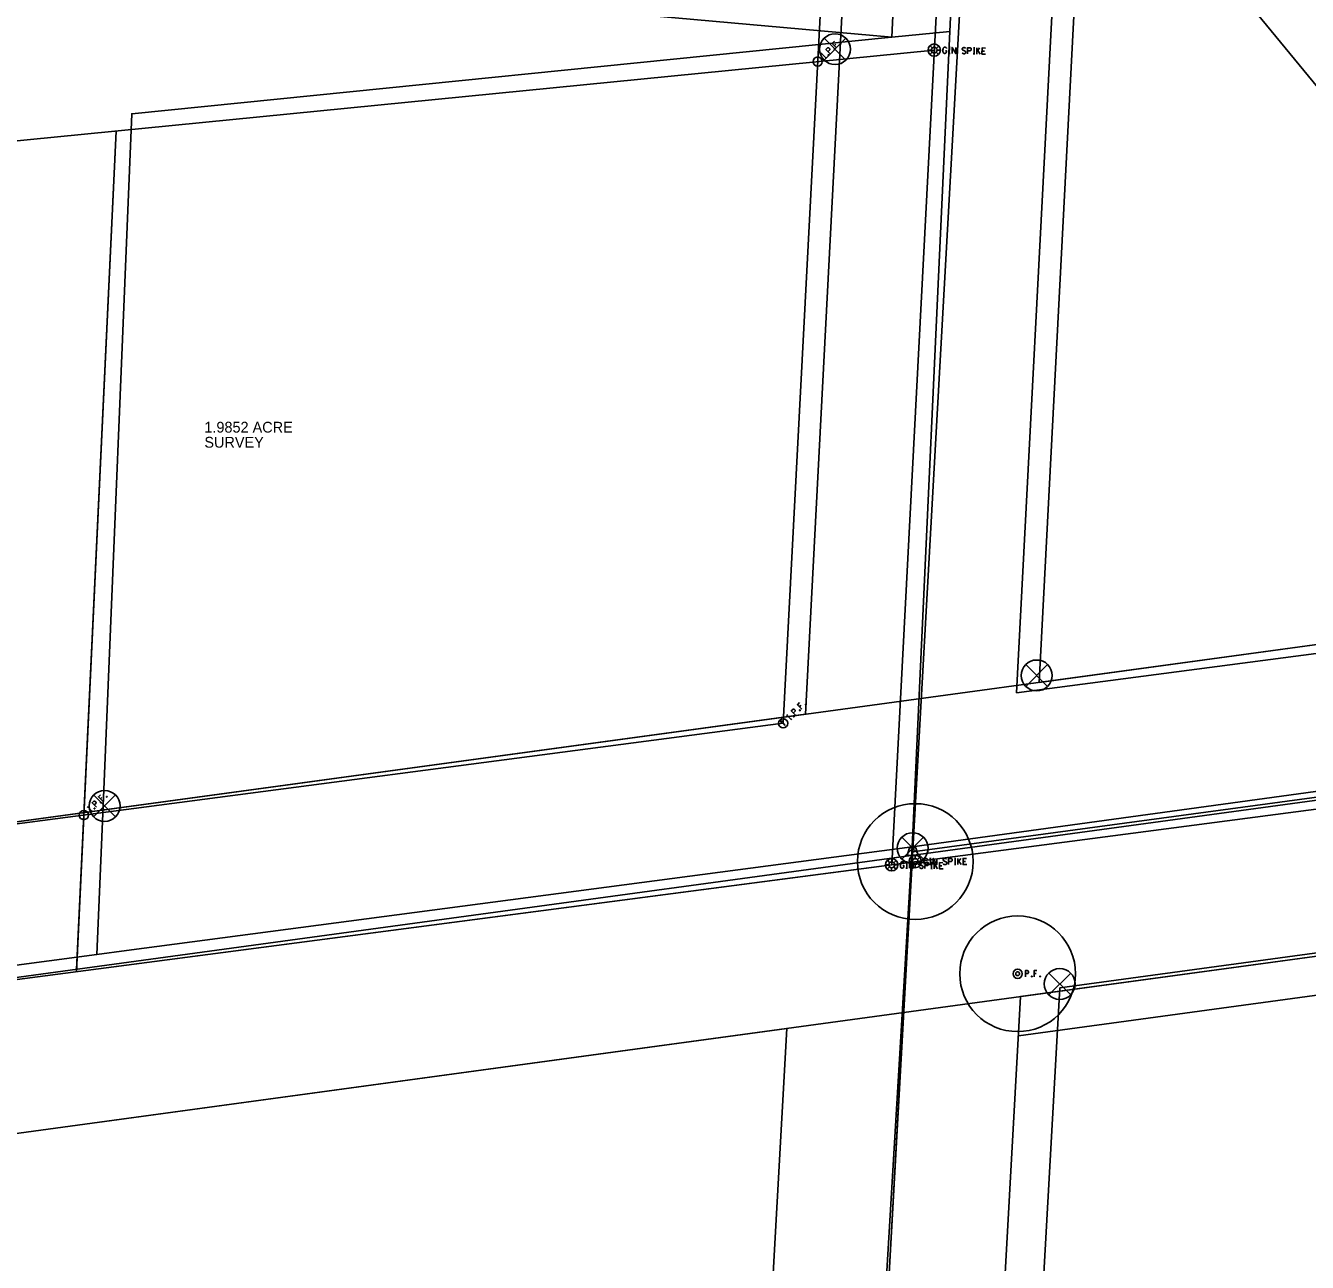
# Model space of a CAD drawing. Extents: x 1532954 to 1577849, y 698998 to 706606.
# Drawn here: x 1571701.2 to 1572033.3, y 702780.4 to 703100.9 of the extents above; entities that cross this region are included whole.
import ezdxf

# ---------------------------------------------------------------- set-up
doc = ezdxf.new("R2010")
doc.units = 0
for name, color, linetype in [('Default', 7, 'Continuous'), ('DV_X_Lot_Line', 7, 'Continuous'), ('GM_X_Major_Lake_Text', 7, 'Continuous'), ('RW_X_Esmt_SH', 7, 'Continuous'), ('RW_X_Esmt_U', 7, 'Continuous'), ('SC_Scratch1', 7, 'Continuous'), ('SC_Scratch10', 7, 'Continuous'), ('SC_Scratch2', 7, 'Continuous'), ('SC_Scratch3', 7, 'Continuous'), ('SC_Scratch9', 7, 'Continuous'), ('SV_X_Control_Cells_Found', 7, 'Continuous'), ('SV_X_Mon_Cells_Found', 7, 'Continuous')]:
    doc.layers.add(name, color=color, linetype=linetype)

msp = doc.modelspace()

# ---------------------------------------------------------------- linework, layer by layer
at = {"layer": 'Default'}
for p, q in [((1571908.1, 703097.6), (1571913.76, 703091.94)), ((1571908.1, 703091.94), (1571913.76, 703097.6)), ((1571910.93, 703094.77), (1571910.93, 703094.77)), ((1571960.35, 702935.33), (1571966.01, 702929.67)), ((1571960.35, 702929.67), (1571966.01, 702935.33)), ((1571963.18, 702932.5), (1571963.18, 702932.5)), ((1571718.87, 702901.53), (1571724.53, 702895.87)), ((1571718.87, 702895.87), (1571724.53, 702901.53)), ((1571721.7, 702898.7), (1571721.7, 702898.7)), ((1571928.21, 702890.57), (1571933.87, 702884.92)), ((1571928.21, 702884.92), (1571933.87, 702890.57)), ((1571931.04, 702887.75), (1571931.04, 702887.75)), ((1571966.32, 702855.4), (1571971.98, 702849.75)), ((1571966.32, 702849.75), (1571971.98, 702855.4)), ((1571969.15, 702852.58), (1571969.15, 702852.58))]:
    msp.add_line(p, q, dxfattribs=at)
for centre in [(1571910.93, 703094.77), (1571963.18, 702932.5), (1571721.7, 702898.7), (1571931.04, 702887.75), (1571969.15, 702852.58)]:
    msp.add_circle(centre, 4, dxfattribs=at)
at = {"layer": 'DV_X_Lot_Line'}
for p, q in [((1571623.65, 703063.55), (1571936.64, 703094.53)), ((1571714.44, 702856.35), (1571724.66, 703073.55))]:
    msp.add_line(p, q, dxfattribs=at)
at = {"layer": 'GM_X_Major_Lake_Text'}
msp.add_line((1571772.95, 700058.9), (1572138.98, 706606.16), dxfattribs=at)
at = {"layer": 'RW_X_Esmt_SH'}
for p, q in [((1571903.27, 702922.46), (1571924.71, 703332.97)), ((1571963.78, 702930.71), (1571984.64, 703330.02)), ((1571959, 702849.32), (1574870.56, 703246.15)), ((1571963.78, 702930.71), (1573359.47, 703120.93)), ((1571490.9, 702866.26), (1571903.27, 702922.46)), ((1571501.71, 702786.99), (1571898.44, 702841.06))]:
    msp.add_line(p, q, dxfattribs=at)
at = {"layer": 'RW_X_Esmt_U'}
for p, q in [((1571958.43, 702839.15), (1572381.44, 702896.8)), ((1571941.24, 702531.66), (1571959, 702849.32)), ((1571881.33, 702535.01), (1571898.44, 702841.06))]:
    msp.add_line(p, q, dxfattribs=at)
at = {"layer": 'SC_Scratch1'}
for points in [[(1571928.39, 703157.53), (1571925.61, 703097.85), (1571726.23, 703115.79), (1571727.99, 703153.75), (1571729.92, 703195.11), (1571729.92, 703195.11), (1571929.3, 703177.17), (1571929.3, 703177.17)], [(1572183.37, 702922.76), (1571930.88, 702888.14), (1571940.7, 703099.36), (1571941.66, 703120.07), (1571956.64, 703119.37), (1572131.42, 703111.24), (1572209.37, 703107.62), (1572202.78, 702965.79), (1572200.89, 702925.16)], [(1571930.88, 702888.14), (1571930.88, 702888.14), (1571727.41, 702861.2), (1571719.71, 702860.18), (1571721.39, 702900.76), (1571728.74, 703078.05), (1571925.59, 703097.85), (1571925.61, 703097.85), (1571940.7, 703099.36)], [(1572165.51, 702622.06), (1571940.9, 702635.26), (1571915.94, 702636.73), (1571918.93, 702687.02), (1571930.88, 702888.14), (1572183.37, 702922.76), (1572180.96, 702882.05)], [(1571418.8, 702820.35), (1571553.44, 702838.18), (1571596.11, 702843.82), (1571719.71, 702860.18), (1571727.41, 702861.2), (1571930.88, 702888.14), (1571930.88, 702888.14), (1571918.93, 702687.02), (1571893.69, 702683.68), (1571718.08, 702660.43), (1571714.44, 702582.22), (1571704.31, 702364.37), (1571672.96, 702360.06), (1571672.96, 702360.06), (1571530.3, 702340.45), (1571347.01, 702315.24), (1571371.42, 702773.73), (1571373.59, 702814.37)]]:
    msp.add_lwpolyline(points, close=True, dxfattribs=at)
at = {"layer": 'SC_Scratch10'}
for p, q in [((1571190.11, 702825.26), (1574958.12, 703338.82)), ((1571190.11, 702825.26), (1574958.12, 703338.82)), ((1571190.11, 702825.26), (1574958.12, 703338.82)), ((1571195.51, 702785.63), (1574963.52, 703299.19)), ((1571200.91, 702745.99), (1574968.92, 703259.55))]:
    msp.add_line(p, q, dxfattribs=at)
at = {"layer": 'SC_Scratch2'}
msp.add_line((1573640.53, 701135.41), (1571969.28, 703165.9), dxfattribs=at)
at = {"layer": 'SC_Scratch3'}
for p, q in [((1571897.48, 702920.1), (1571919.07, 703333.38)), ((1571925.61, 702883.45), (1571949.03, 703331.81)), ((1571957.98, 702928.04), (1571978.99, 703330.34)), ((1571938.76, 703135.11), (1571925.61, 702883.46)), ((1571908.52, 703131.35), (1571897.49, 702920.1)), ((1571566.93, 703057.93), (1571936.64, 703094.53)), ((1571935.89, 703094.54), (1571935.04, 703094.56)), ((1571936.09, 703094.01), (1571935.48, 703093.42)), ((1571936.12, 703095.07), (1571935.53, 703095.68)), ((1571936.62, 703093.78), (1571936.6, 703092.93)), ((1571936.65, 703095.28), (1571936.67, 703096.12)), ((1571937.16, 703093.98), (1571937.74, 703093.37)), ((1571937.18, 703095.04), (1571937.79, 703095.63)), ((1571937.39, 703094.51), (1571938.24, 703094.49)), ((1571714.41, 702855.73), (1571724.66, 703073.54)), ((1571931.04, 702886.78), (1572682.15, 702988.83)), ((1572198.25, 702959.58), (1571957.98, 702928.04)), ((1571931.04, 702886.78), (1572375.46, 702947.16)), ((1572196.13, 702918.96), (1571335.92, 702806.05)), ((1571897.48, 702920.1), (1571586.45, 702879.28)), ((1571897.49, 702920.1), (1571586.45, 702879.28)), ((1571897.4, 702920.19), (1571898.03, 702919.56)), ((1571969.14, 702851.59), (1572380.18, 702907.43)), ((1571931.05, 702887.87), (1571931.05, 702887.27)), ((1571816.39, 700835.98), (1571931.04, 702886.78)), ((1571925.09, 702883.99), (1571924.5, 702884.61)), ((1571925.63, 702884.2), (1571925.64, 702885.05)), ((1571926.15, 702883.97), (1571926.76, 702884.56)), ((1571925.61, 702883.45), (1571590.79, 702839.51)), ((1571924.86, 702883.47), (1571924.01, 702883.49)), ((1571925.07, 702882.93), (1571924.46, 702882.34)), ((1571925.6, 702882.7), (1571925.58, 702881.85)), ((1571926.13, 702882.91), (1571926.72, 702882.3)), ((1571926.36, 702883.44), (1571927.21, 702883.42)), ((1571856.33, 700833.75), (1571969.14, 702851.59))]:
    msp.add_line(p, q, dxfattribs=at)
for points in [[(1571910.76, 703096.8), (1571910.22, 703096.27), (1571911.32, 703095.12)], [(1571907.34, 703093.51), (1571907.59, 703093.75)], [(1571908.57, 703092.48), (1571907.46, 703093.63)], [(1571909.7, 703093.56), (1571908.59, 703094.71), (1571908.98, 703095.08), (1571909.02, 703095.11), (1571909.1, 703095.15), (1571909.14, 703095.15), (1571909.18, 703095.15), (1571909.25, 703095.14), (1571909.32, 703095.12), (1571909.41, 703095.06), (1571909.51, 703094.95), (1571909.54, 703094.91), (1571909.58, 703094.84), (1571909.61, 703094.74), (1571909.6, 703094.69), (1571909.59, 703094.64), (1571909.57, 703094.59), (1571909.52, 703094.52), (1571909.13, 703094.15)], [(1571910.74, 703094.85), (1571910.78, 703094.89), (1571910.82, 703094.9), (1571910.88, 703094.88), (1571910.92, 703094.84), (1571910.93, 703094.78), (1571910.93, 703094.74), (1571910.89, 703094.7), (1571910.85, 703094.69), (1571910.79, 703094.71), (1571910.74, 703094.75), (1571910.73, 703094.81), (1571910.74, 703094.85)], [(1571910.76, 703095.71), (1571911.15, 703096.08)], [(1571912.29, 703096.34), (1571912.33, 703096.38), (1571912.37, 703096.38), (1571912.43, 703096.37), (1571912.47, 703096.33), (1571912.48, 703096.27), (1571912.48, 703096.23), (1571912.44, 703096.19), (1571912.4, 703096.18), (1571912.34, 703096.2), (1571912.29, 703096.24), (1571912.28, 703096.3), (1571912.29, 703096.34)], [(1571939.83, 703094.95), (1571939.82, 703095.01), (1571939.78, 703095.07), (1571939.72, 703095.14), (1571939.64, 703095.21), (1571939.57, 703095.24), (1571939.52, 703095.25), (1571939.45, 703095.27), (1571939.3, 703095.27), (1571939.23, 703095.26), (1571939.2, 703095.25), (1571939.15, 703095.22), (1571939.04, 703095.15), (1571938.98, 703095.06), (1571938.94, 703094.96), (1571938.91, 703094.83), (1571938.88, 703094.62), (1571938.88, 703094.36), (1571938.88, 703094.15), (1571938.93, 703093.98), (1571939, 703093.83), (1571939.07, 703093.78), (1571939.14, 703093.72), (1571939.28, 703093.67), (1571939.42, 703093.67), (1571939.56, 703093.69), (1571939.61, 703093.72), (1571939.66, 703093.74), (1571939.71, 703093.79), (1571939.76, 703093.86), (1571939.81, 703093.98), (1571939.82, 703094.29), (1571939.55, 703094.3)], [(1571940.34, 703093.65), (1571940.74, 703093.64)], [(1571940.37, 703095.25), (1571940.77, 703095.24)], [(1571940.54, 703093.65), (1571940.57, 703095.25)], [(1571941.24, 703093.63), (1571941.27, 703095.23), (1571942.19, 703093.61), (1571942.22, 703095.21)], [(1571944.74, 703095.05), (1571944.71, 703095.07), (1571944.67, 703095.1), (1571944.56, 703095.14), (1571944.42, 703095.17), (1571944.32, 703095.17), (1571944.28, 703095.17), (1571944.12, 703095.14), (1571943.98, 703095.06), (1571943.89, 703094.96), (1571943.86, 703094.86), (1571943.86, 703094.79), (1571943.88, 703094.69), (1571943.98, 703094.6), (1571944.67, 703094.21), (1571944.73, 703094.15), (1571944.75, 703094.1), (1571944.78, 703094.03), (1571944.78, 703093.95), (1571944.76, 703093.88), (1571944.75, 703093.83), (1571944.72, 703093.76), (1571944.7, 703093.71), (1571944.67, 703093.68), (1571944.63, 703093.64), (1571944.59, 703093.61), (1571944.54, 703093.59), (1571944.5, 703093.58), (1571944.39, 703093.57), (1571944.21, 703093.57), (1571944.1, 703093.6), (1571943.94, 703093.69), (1571943.84, 703093.77)], [(1571945.25, 703093.55), (1571945.28, 703095.15), (1571945.88, 703095.14), (1571945.95, 703095.12), (1571946.03, 703095.1), (1571946.07, 703095.07), (1571946.11, 703095.05), (1571946.16, 703094.98), (1571946.19, 703094.92), (1571946.22, 703094.82), (1571946.21, 703094.67), (1571946.2, 703094.62), (1571946.17, 703094.54), (1571946.12, 703094.45), (1571946.07, 703094.42), (1571946.03, 703094.39), (1571945.97, 703094.37), (1571945.87, 703094.36), (1571945.26, 703094.37)], [(1571946.73, 703093.52), (1571947.14, 703093.51)], [(1571946.77, 703095.12), (1571947.17, 703095.11)], [(1571946.94, 703093.52), (1571946.97, 703095.12)], [(1571947.67, 703095.1), (1571947.64, 703093.5)], [(1571948.4, 703095.09), (1571947.65, 703094.08)], [(1571947.9, 703094.4), (1571948.5, 703093.49)], [(1571949.9, 703095.06), (1571949.03, 703095.07), (1571949, 703093.48), (1571949.93, 703093.46)], [(1571949.02, 703094.28), (1571949.63, 703094.27)], [(1571908.45, 703092.35), (1571908.7, 703092.6)], [(1571909.12, 703093.3), (1571909.16, 703093.33), (1571909.2, 703093.34), (1571909.26, 703093.32), (1571909.3, 703093.28), (1571909.31, 703093.22), (1571909.3, 703093.18), (1571909.26, 703093.14), (1571909.22, 703093.14), (1571909.16, 703093.15), (1571909.12, 703093.19), (1571909.11, 703093.25), (1571909.12, 703093.3)], [(1571901.72, 702925.46), (1571901.18, 702924.93), (1571902.31, 702923.79)], [(1571901.73, 702924.37), (1571902.11, 702924.76)], [(1571903.25, 702925.04), (1571903.29, 702925.08), (1571903.33, 702925.08), (1571903.39, 702925.07), (1571903.43, 702925.02), (1571903.45, 702924.97), (1571903.44, 702924.92), (1571903.4, 702924.89), (1571903.36, 702924.88), (1571903.3, 702924.89), (1571903.26, 702924.94), (1571903.24, 702925), (1571903.25, 702925.04)], [(1571898.36, 702922.11), (1571898.61, 702922.35)], [(1571899.61, 702921.1), (1571898.48, 702922.23)], [(1571899.49, 702920.97), (1571899.74, 702921.22)], [(1571900.72, 702922.21), (1571899.59, 702923.34), (1571899.96, 702923.71), (1571900.01, 702923.74), (1571900.08, 702923.78), (1571900.12, 702923.78), (1571900.17, 702923.79), (1571900.24, 702923.78), (1571900.31, 702923.75), (1571900.4, 702923.7), (1571900.5, 702923.59), (1571900.53, 702923.55), (1571900.57, 702923.48), (1571900.6, 702923.39), (1571900.59, 702923.33), (1571900.59, 702923.29), (1571900.57, 702923.23), (1571900.51, 702923.16), (1571900.14, 702922.78)], [(1571900.14, 702921.93), (1571900.18, 702921.97), (1571900.22, 702921.97), (1571900.28, 702921.96), (1571900.32, 702921.92), (1571900.34, 702921.86), (1571900.33, 702921.82), (1571900.29, 702921.78), (1571900.25, 702921.77), (1571900.19, 702921.78), (1571900.15, 702921.83), (1571900.13, 702921.89), (1571900.14, 702921.93)], [(1571901.73, 702923.52), (1571901.77, 702923.56), (1571901.81, 702923.56), (1571901.87, 702923.55), (1571901.91, 702923.51), (1571901.93, 702923.45), (1571901.92, 702923.41), (1571901.88, 702923.37), (1571901.84, 702923.36), (1571901.78, 702923.37), (1571901.74, 702923.42), (1571901.72, 702923.48), (1571901.73, 702923.52)], [(1571720.65, 702901.59), (1571720.1, 702901.06), (1571721.21, 702899.91)], [(1571720.64, 702900.5), (1571721.03, 702900.87)], [(1571722.17, 702901.13), (1571722.21, 702901.17), (1571722.25, 702901.17), (1571722.31, 702901.16), (1571722.35, 702901.12), (1571722.37, 702901.06), (1571722.36, 702901.02), (1571722.32, 702900.98), (1571722.28, 702900.97), (1571722.22, 702900.99), (1571722.18, 702901.03), (1571722.16, 702901.09), (1571722.17, 702901.13)], [(1571717.22, 702898.3), (1571717.47, 702898.54)], [(1571718.46, 702897.27), (1571717.35, 702898.42)], [(1571719.58, 702898.35), (1571718.48, 702899.5), (1571718.86, 702899.87), (1571718.91, 702899.9), (1571718.98, 702899.94), (1571719.02, 702899.94), (1571719.06, 702899.94), (1571719.14, 702899.93), (1571719.21, 702899.91), (1571719.29, 702899.85), (1571719.4, 702899.74), (1571719.42, 702899.7), (1571719.46, 702899.63), (1571719.49, 702899.53), (1571719.48, 702899.48), (1571719.48, 702899.43), (1571719.45, 702899.38), (1571719.4, 702899.31), (1571719.02, 702898.94)], [(1571719, 702898.09), (1571719.04, 702898.12), (1571719.08, 702898.13), (1571719.14, 702898.11), (1571719.18, 702898.07), (1571719.19, 702898.01), (1571719.19, 702897.97), (1571719.15, 702897.93), (1571719.11, 702897.93), (1571719.05, 702897.94), (1571719, 702897.98), (1571718.99, 702898.04), (1571719, 702898.09)], [(1571720.62, 702899.64), (1571720.66, 702899.68), (1571720.7, 702899.69), (1571720.76, 702899.67), (1571720.8, 702899.63), (1571720.82, 702899.57), (1571720.81, 702899.53), (1571720.77, 702899.49), (1571720.73, 702899.48), (1571720.67, 702899.5), (1571720.63, 702899.54), (1571720.61, 702899.6), (1571720.62, 702899.64)], [(1571718.33, 702897.14), (1571718.58, 702897.39)], [(1571928.81, 702883.87), (1571928.8, 702883.94), (1571928.76, 702884), (1571928.7, 702884.06), (1571928.61, 702884.14), (1571928.55, 702884.17), (1571928.5, 702884.18), (1571928.42, 702884.2), (1571928.27, 702884.2), (1571928.21, 702884.19), (1571928.17, 702884.18), (1571928.12, 702884.15), (1571928.02, 702884.08), (1571927.95, 702883.99), (1571927.91, 702883.89), (1571927.89, 702883.75), (1571927.86, 702883.55), (1571927.85, 702883.29), (1571927.86, 702883.07), (1571927.91, 702882.91), (1571927.98, 702882.76), (1571928.04, 702882.7), (1571928.11, 702882.65), (1571928.25, 702882.6), (1571928.39, 702882.6), (1571928.53, 702882.62), (1571928.58, 702882.64), (1571928.63, 702882.67), (1571928.68, 702882.72), (1571928.73, 702882.79), (1571928.79, 702882.9), (1571928.79, 702883.22), (1571928.53, 702883.22)], [(1571929.34, 702884.18), (1571929.75, 702884.17)], [(1571929.51, 702882.57), (1571929.54, 702884.17)], [(1571930.22, 702882.56), (1571930.25, 702884.16), (1571931.16, 702882.54), (1571931.19, 702884.14)], [(1571929.31, 702882.58), (1571929.71, 702882.57)], [(1571933.71, 702883.98), (1571933.69, 702884), (1571933.65, 702884.03), (1571933.54, 702884.07), (1571933.4, 702884.1), (1571933.3, 702884.1), (1571933.26, 702884.1), (1571933.09, 702884.06), (1571932.95, 702883.99), (1571932.86, 702883.89), (1571932.84, 702883.79), (1571932.84, 702883.72), (1571932.86, 702883.62), (1571932.96, 702883.52), (1571933.64, 702883.13), (1571933.71, 702883.08), (1571933.73, 702883.03), (1571933.75, 702882.95), (1571933.75, 702882.88), (1571933.74, 702882.8), (1571933.72, 702882.75), (1571933.7, 702882.69), (1571933.67, 702882.64), (1571933.65, 702882.6), (1571933.61, 702882.57), (1571933.57, 702882.54), (1571933.52, 702882.52), (1571933.48, 702882.51), (1571933.37, 702882.5), (1571933.19, 702882.5), (1571933.08, 702882.53), (1571932.91, 702882.62), (1571932.82, 702882.7)], [(1571934.22, 702882.48), (1571934.25, 702884.08), (1571934.86, 702884.07), (1571934.92, 702884.05), (1571935.01, 702884.03), (1571935.05, 702884), (1571935.08, 702883.97), (1571935.13, 702883.91), (1571935.17, 702883.85), (1571935.19, 702883.74), (1571935.19, 702883.59), (1571935.18, 702883.54), (1571935.15, 702883.47), (1571935.1, 702883.38), (1571935.05, 702883.34), (1571935.01, 702883.32), (1571934.94, 702883.3), (1571934.84, 702883.29), (1571934.24, 702883.3)], [(1571935.71, 702882.45), (1571936.11, 702882.44)], [(1571935.74, 702884.05), (1571936.14, 702884.04)], [(1571935.91, 702882.44), (1571935.94, 702884.04)], [(1571936.65, 702884.03), (1571936.62, 702882.43)], [(1571937.38, 702884.02), (1571936.63, 702883.01)], [(1571936.87, 702883.33), (1571937.47, 702882.41)], [(1571938.88, 702883.99), (1571938.01, 702884), (1571937.98, 702882.4), (1571938.91, 702882.38)], [(1571937.99, 702883.21), (1571938.61, 702883.2)]]:
    msp.add_lwpolyline(points, dxfattribs=at)
msp.add_lwpolyline([(1571929.63, 702885.88), (1571932.44, 702885.86), (1571931.86, 702887.86), (1571930.25, 702887.88)], close=True, dxfattribs=at)
for centre, radius in [((1571936.64, 703094.53), 1.6), ((1571936.64, 703094.53), 0.75), ((1571906.44, 703091.54), 1.2), ((1571897.49, 702920.1), 1.2), ((1571897.03, 702920.57), 0.16), ((1571716.32, 702896.33), 1.2), ((1571925.61, 702883.45), 1.6), ((1571925.61, 702883.45), 0.75)]:
    msp.add_circle(centre, radius, dxfattribs=at)
at = {"layer": 'SC_Scratch9'}
for centre in [(1571931.73, 702884.28), (1571958.24, 702855.22)]:
    msp.add_circle(centre, 15, dxfattribs=at)
at = {"layer": 'SV_X_Control_Cells_Found'}
for p, q in [((1571930.98, 702884.28), (1571930.13, 702884.28)), ((1571931.2, 702884.81), (1571930.6, 702885.41)), ((1571931.73, 702885.03), (1571931.73, 702885.88)), ((1571932.26, 702884.81), (1571932.87, 702885.41)), ((1571932.48, 702884.28), (1571933.33, 702884.28)), ((1571931.2, 702883.75), (1571930.6, 702883.14)), ((1571931.73, 702883.53), (1571931.73, 702882.68)), ((1571932.26, 702883.75), (1571932.87, 702883.14))]:
    msp.add_line(p, q, dxfattribs=at)
for points in [[(1571934.92, 702884.76), (1571934.91, 702884.82), (1571934.87, 702884.89), (1571934.81, 702884.95), (1571934.72, 702885.03), (1571934.66, 702885.05), (1571934.61, 702885.06), (1571934.53, 702885.08), (1571934.38, 702885.08), (1571934.32, 702885.06), (1571934.28, 702885.05), (1571934.23, 702885.03), (1571934.13, 702884.95), (1571934.07, 702884.86), (1571934.03, 702884.76), (1571934, 702884.62), (1571933.98, 702884.42), (1571933.98, 702884.16), (1571933.99, 702883.94), (1571934.04, 702883.78), (1571934.12, 702883.63), (1571934.18, 702883.58), (1571934.25, 702883.53), (1571934.39, 702883.48), (1571934.53, 702883.48), (1571934.67, 702883.5), (1571934.72, 702883.53), (1571934.77, 702883.55), (1571934.82, 702883.6), (1571934.87, 702883.68), (1571934.92, 702883.79), (1571934.92, 702884.11), (1571934.66, 702884.11)], [(1571935.45, 702885.08), (1571935.85, 702885.08)], [(1571935.65, 702883.48), (1571935.65, 702885.08)], [(1571936.36, 702883.48), (1571936.36, 702885.08), (1571937.3, 702883.48), (1571937.3, 702885.08)], [(1571939.82, 702884.96), (1571939.8, 702884.99), (1571939.76, 702885.01), (1571939.65, 702885.05), (1571939.51, 702885.08), (1571939.41, 702885.08), (1571939.37, 702885.08), (1571939.2, 702885.04), (1571939.07, 702884.96), (1571938.98, 702884.86), (1571938.95, 702884.76), (1571938.95, 702884.69), (1571938.98, 702884.58), (1571939.08, 702884.5), (1571939.77, 702884.12), (1571939.83, 702884.07), (1571939.86, 702884.02), (1571939.89, 702883.94), (1571939.89, 702883.87), (1571939.87, 702883.79), (1571939.86, 702883.74), (1571939.83, 702883.68), (1571939.81, 702883.63), (1571939.78, 702883.59), (1571939.75, 702883.55), (1571939.71, 702883.53), (1571939.66, 702883.5), (1571939.62, 702883.49), (1571939.51, 702883.48), (1571939.33, 702883.48), (1571939.22, 702883.5), (1571939.05, 702883.59), (1571938.95, 702883.66)], [(1571940.36, 702883.48), (1571940.36, 702885.08), (1571940.97, 702885.08), (1571941.03, 702885.06), (1571941.12, 702885.04), (1571941.16, 702885.01), (1571941.2, 702884.99), (1571941.25, 702884.92), (1571941.28, 702884.86), (1571941.31, 702884.76), (1571941.31, 702884.61), (1571941.3, 702884.56), (1571941.27, 702884.48), (1571941.22, 702884.4), (1571941.17, 702884.36), (1571941.13, 702884.33), (1571941.07, 702884.31), (1571940.97, 702884.29), (1571940.36, 702884.29)], [(1571941.85, 702885.08), (1571942.25, 702885.08)], [(1571942.05, 702883.48), (1571942.05, 702885.08)], [(1571942.76, 702885.08), (1571942.76, 702883.48)], [(1571943.49, 702885.08), (1571942.76, 702884.06)], [(1571943, 702884.38), (1571943.61, 702883.48)], [(1571944.99, 702885.08), (1571944.12, 702885.08), (1571944.12, 702883.48), (1571945.05, 702883.48)], [(1571944.12, 702884.28), (1571944.74, 702884.28)], [(1571935.45, 702883.48), (1571935.85, 702883.48)], [(1571941.85, 702883.48), (1571942.25, 702883.48)]]:
    msp.add_lwpolyline(points, dxfattribs=at)
for radius in [1.6, 0.75]:
    msp.add_circle((1571931.73, 702884.28), radius, dxfattribs=at)
at = {"layer": 'SV_X_Mon_Cells_Found'}
for points in [[(1571960.24, 702854.42), (1571960.24, 702856.02), (1571960.77, 702856.02), (1571960.82, 702856), (1571960.9, 702855.98), (1571960.93, 702855.95), (1571960.97, 702855.93), (1571961.01, 702855.86), (1571961.04, 702855.8), (1571961.07, 702855.7), (1571961.07, 702855.55), (1571961.06, 702855.5), (1571961.03, 702855.42), (1571960.99, 702855.34), (1571960.95, 702855.3), (1571960.91, 702855.27), (1571960.86, 702855.25), (1571960.77, 702855.24), (1571960.24, 702855.24)], [(1571961.88, 702854.63), (1571961.94, 702854.63), (1571961.97, 702854.61), (1571962, 702854.55), (1571962, 702854.49), (1571961.97, 702854.44), (1571961.94, 702854.42), (1571961.88, 702854.42), (1571961.85, 702854.44), (1571961.82, 702854.49), (1571961.82, 702854.55), (1571961.85, 702854.61), (1571961.88, 702854.63)], [(1571963.25, 702856.02), (1571962.49, 702856.02), (1571962.49, 702854.42)], [(1571962.49, 702855.24), (1571963.03, 702855.24)], [(1571964.03, 702854.63), (1571964.09, 702854.63), (1571964.12, 702854.61), (1571964.15, 702854.55), (1571964.15, 702854.49), (1571964.12, 702854.44), (1571964.09, 702854.42), (1571964.03, 702854.42), (1571964, 702854.44), (1571963.97, 702854.49), (1571963.97, 702854.55), (1571964, 702854.61), (1571964.03, 702854.63)]]:
    msp.add_lwpolyline(points, dxfattribs=at)
for radius in [1.2, 0.495]:
    msp.add_circle((1571958.24, 702855.22), radius, dxfattribs=at)

# ---------------------------------------------------------------- texts
at = {"layer": 'SC_Scratch3'}
for s, p in [('1.9852 ACRE', (1571747.55, 702995.42)), ('SURVEY', (1571747.55, 702991.52))]:
    msp.add_text(s, height=2.8, rotation=359.9849, dxfattribs=at).set_placement(p)

doc.saveas('drawing.dxf')
